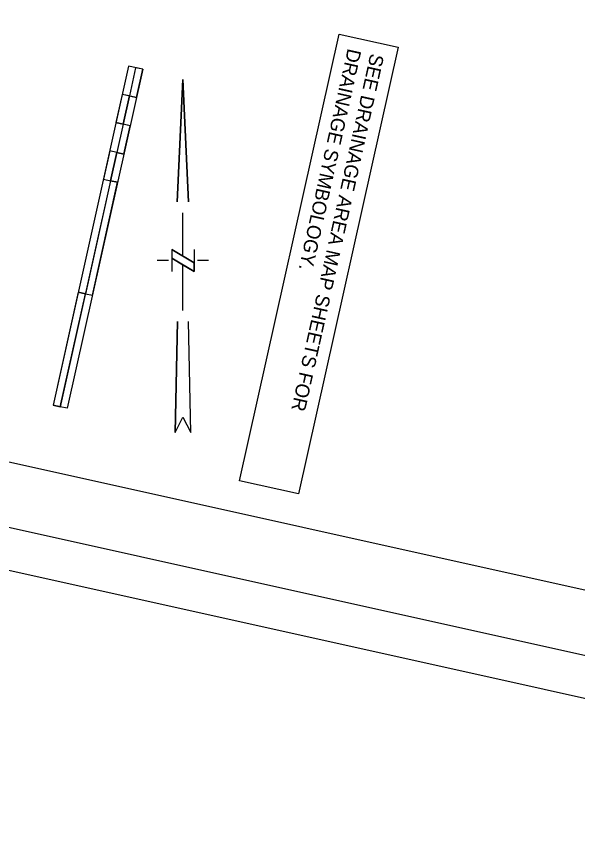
# Model space of a CAD drawing. Extents: x 2149268 to 2150830, y 142155 to 144285.
# Drawn here: x 2149919.9 to 2150161.5, y 142154.7 to 142509.8 of the extents above; entities that cross this region are included whole.
import ezdxf

# ---------------------------------------------------------------- set-up
doc = ezdxf.new("R2010")
doc.units = 0
for name, color, linetype in [('PR_Storm_Txt', 7, 'Continuous'), ('SHT_North_Arrow', 7, 'Continuous'), ('SHT_Plot_Shape_Full', 7, 'Continuous'), ('SHT_Plot_Shape_Half', 7, 'Continuous'), ('SHT_Scale', 7, 'Continuous'), ('SHT_Sheet_Border', 7, 'Continuous')]:
    doc.layers.add(name, color=color, linetype=linetype)

msp = doc.modelspace()

# ---------------------------------------------------------------- linework, layer by layer
at = {"layer": 'PR_Storm_Txt'}
msp.add_lwpolyline([(2150084.18, 142496.56), (2150041.37, 142304.05), (2150015.97, 142309.7), (2150058.78, 142502.21)], close=True, dxfattribs=at)
at = {"layer": 'SHT_North_Arrow'}
for p, q in [((2149989.16, 142429.9), (2149991.54, 142482.67)), ((2149991.54, 142482.67), (2149989.16, 142429.9)), ((2149991.54, 142482.67), (2149993.97, 142429.91)), ((2149993.97, 142429.91), (2149991.54, 142482.67)), ((2149991.57, 142406.57), (2149991.57, 142425.24)), ((2149996.37, 142403.7), (2149986.77, 142409.44)), ((2149986.77, 142409.44), (2149996.37, 142403.7)), ((2149986.77, 142409.44), (2149986.78, 142399.87)), ((2149991.57, 142406.57), (2149986.77, 142409.44)), ((2149986.77, 142409.44), (2149986.78, 142405.61)), ((2149996.37, 142409.44), (2149996.37, 142399.87)), ((2149996.37, 142399.87), (2149986.78, 142405.61)), ((2149996.37, 142403.7), (2149991.57, 142406.57)), ((2149985.34, 142404.66), (2149980.54, 142404.66)), ((2149991.58, 142383.12), (2149991.57, 142402.74)), ((2149996.37, 142399.87), (2149996.37, 142403.7)), ((2150002.61, 142404.66), (2149997.81, 142404.66)), ((2149988.25, 142330.48), (2149989.19, 142378.34)), ((2149989.19, 142378.34), (2149988.25, 142330.48)), ((2149994.96, 142330.48), (2149993.98, 142378.34)), ((2149994.96, 142330.48), (2149993.98, 142378.34)), ((2149988.25, 142330.48), (2149991.6, 142337.18)), ((2149988.25, 142330.48), (2149991.6, 142337.18)), ((2149991.6, 142337.18), (2149994.96, 142330.48)), ((2149991.6, 142337.18), (2149994.96, 142330.48))]:
    msp.add_line(p, q, dxfattribs=at)
for points in [[(2149986.78, 142405.61), (2149991.57, 142402.74), (2149996.37, 142399.87)], [(2149991.59, 142383.12), (2149991.58, 142383.12), (2149991.58, 142383.12)]]:
    msp.add_lwpolyline(points, dxfattribs=at)
at = {"layer": 'SHT_Plot_Shape_Full'}
msp.add_lwpolyline([(2150830.28, 143911.83), (2150439.58, 142154.75), (2149268.19, 142415.21), (2149658.89, 144172.3)], close=True, dxfattribs=at)
at = {"layer": 'SHT_Plot_Shape_Half'}
msp.add_lwpolyline([(2150772.24, 143840.86), (2150403.25, 142181.39), (2149329.47, 142420.15), (2149698.47, 144079.62)], close=True, dxfattribs=at)
at = {"layer": 'SHT_Scale'}
for p, q in [((2149968.17, 142488.38), (2149935.69, 142342.31)), ((2149974.27, 142487.02), (2149941.79, 142340.96)), ((2149974.27, 142487.02), (2149968.17, 142488.38)), ((2149971.22, 142487.7), (2149968.51, 142475.53)), ((2149971.22, 142487.7), (2149968.51, 142475.53)), ((2149974.27, 142487.02), (2149971.22, 142487.7)), ((2149971.56, 142474.85), (2149974.27, 142487.02)), ((2149965.46, 142476.21), (2149962.76, 142464.04)), ((2149971.56, 142474.85), (2149965.46, 142476.21)), ((2149968.51, 142475.53), (2149965.46, 142476.21)), ((2149968.51, 142475.53), (2149965.81, 142463.36)), ((2149965.81, 142463.36), (2149968.51, 142475.53)), ((2149968.51, 142475.53), (2149971.56, 142474.85)), ((2149968.86, 142462.68), (2149962.76, 142464.04)), ((2149968.86, 142462.68), (2149962.76, 142464.04)), ((2149962.76, 142464.04), (2149965.81, 142463.36)), ((2149965.81, 142463.36), (2149963.1, 142451.19)), ((2149965.81, 142463.36), (2149963.1, 142451.19)), ((2149968.86, 142462.68), (2149965.81, 142463.36)), ((2149966.15, 142450.51), (2149968.86, 142462.68)), ((2149960.05, 142451.86), (2149957.34, 142439.69)), ((2149966.15, 142450.51), (2149960.05, 142451.86)), ((2149963.1, 142451.19), (2149960.05, 142451.86)), ((2149963.1, 142451.19), (2149960.39, 142439.01)), ((2149960.39, 142439.01), (2149963.1, 142451.19)), ((2149963.1, 142451.19), (2149966.15, 142450.51)), ((2149960.39, 142439.01), (2149938.74, 142341.64)), ((2149960.39, 142439.01), (2149949.57, 142390.33)), ((2149952.62, 142389.65), (2149963.44, 142438.34)), ((2149957.34, 142439.69), (2149960.39, 142439.01)), ((2149957.34, 142439.69), (2149960.39, 142439.01)), ((2149960.39, 142439.01), (2149963.44, 142438.34)), ((2149963.44, 142438.34), (2149960.39, 142439.01)), ((2149946.52, 142391), (2149935.69, 142342.31)), ((2149946.52, 142391), (2149949.57, 142390.33)), ((2149949.57, 142390.33), (2149946.52, 142391)), ((2149938.74, 142341.64), (2149949.57, 142390.33)), ((2149949.57, 142390.33), (2149952.62, 142389.65)), ((2149949.57, 142390.33), (2149952.62, 142389.65)), ((2149938.74, 142341.64), (2149935.69, 142342.31)), ((2149935.69, 142342.31), (2149938.74, 142341.64)), ((2149941.79, 142340.96), (2149938.74, 142341.64))]:
    msp.add_line(p, q, dxfattribs=at)
at = {"layer": 'SHT_Sheet_Border'}
msp.add_lwpolyline([(2150726.67, 143751.11), (2150384.81, 142213.66), (2149359.84, 142441.57), (2149701.71, 143979.02)], close=True, dxfattribs=at)

# ---------------------------------------------------------------- texts
at = {"layer": 'PR_Storm_Txt'}
for s, p in [('DRAINAGE SYMBOLOGY.', (2150062.58, 142496.24)), ('SEE DRAINAGE AREA MAP SHEETS FOR', (2150072.36, 142494.07))]:
    msp.add_text(s, height=6, rotation=257.4638, dxfattribs=at).set_placement(p)

doc.saveas('drawing.dxf')
